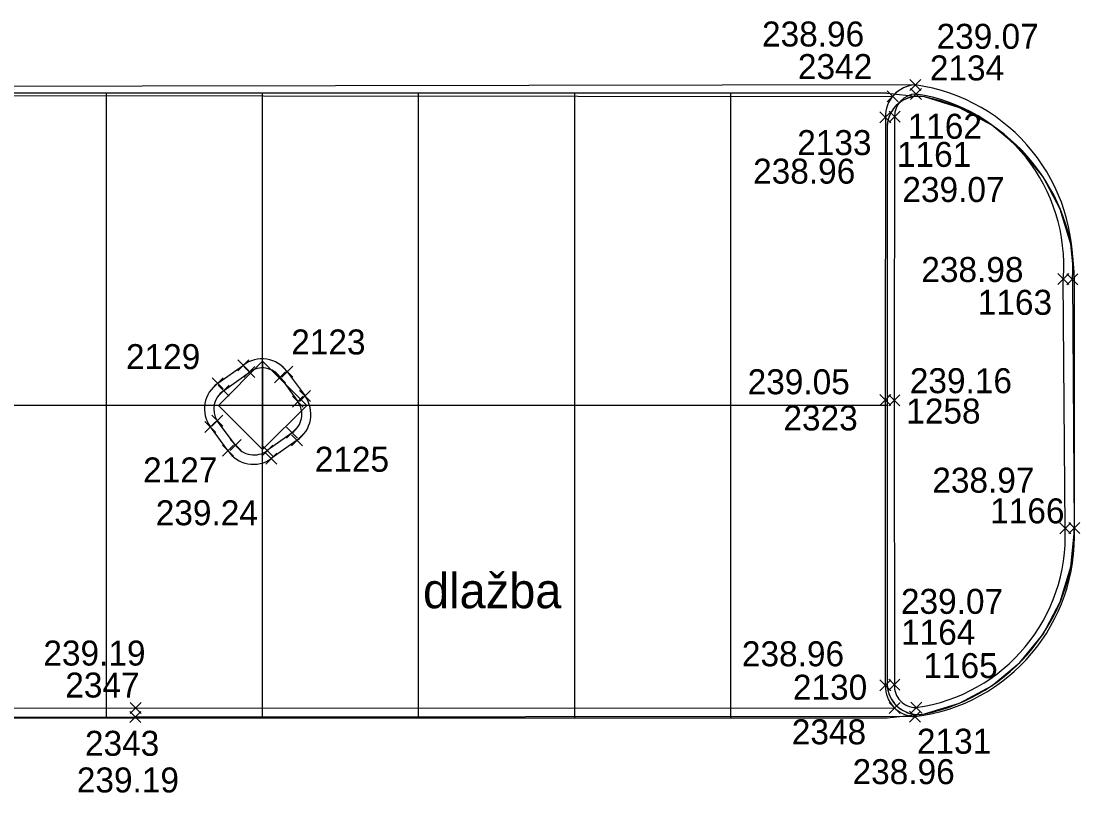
# Model space of a CAD drawing. Extents: x -264222 to -263676, y -1242344 to -1242060.
# Drawn here: x -264148.43 to -264131.48, y -1242229.68 to -1242217.33 of the extents above; entities that cross this region are included whole.
import ezdxf

# ---------------------------------------------------------------- set-up
doc = ezdxf.new("R2010")
doc.units = 0
for name, color, linetype in [('BODY_CISLO', 7, 'Continuous'), ('BODY_SYMBOL', 7, 'Continuous'), ('BODY_VYSKA', 7, 'Continuous'), ('KOORDINACNA_SITUACIA_DSP', 7, 'Continuous'), ('POPIS', 7, 'Continuous'), ('PROJEKT_DRS_OBRUBNIKY_KOMUNIKACIE', 7, 'Continuous'), ('PROJEKT_DRS_TDZ_VODOROVNE', 7, 'Continuous'), ('SO_20-3_OBRUBNIKY_DOLNA_HRANA', 7, 'Continuous'), ('SO_20-3_OBRUBNIKY_HORNA_HRANA', 7, 'Continuous')]:
    doc.layers.add(name, color=color, linetype=linetype)

msp = doc.modelspace()

# ---------------------------------------------------------------- linework, layer by layer
at = {"layer": 'BODY_SYMBOL'}
for p, q in [((-264134.201, -1242218.439), (-264134.025, -1242218.263)), ((-264134.025, -1242218.439), (-264134.201, -1242218.263)), ((-264134.567, -1242218.621), (-264134.391, -1242218.445)), ((-264134.391, -1242218.621), (-264134.567, -1242218.445)), ((-264134.191, -1242218.584), (-264134.015, -1242218.408)), ((-264134.015, -1242218.584), (-264134.191, -1242218.408)), ((-264134.683, -1242218.959), (-264134.507, -1242218.783)), ((-264134.507, -1242218.959), (-264134.683, -1242218.783)), ((-264134.534, -1242218.947), (-264134.358, -1242218.771)), ((-264134.358, -1242218.947), (-264134.534, -1242218.771)), ((-264131.834, -1242221.548), (-264131.658, -1242221.372)), ((-264131.658, -1242221.548), (-264131.834, -1242221.372)), ((-264131.688, -1242221.552), (-264131.512, -1242221.376)), ((-264131.512, -1242221.552), (-264131.688, -1242221.376)), ((-264144.963, -1242222.926), (-264144.787, -1242222.75)), ((-264144.787, -1242222.926), (-264144.963, -1242222.75)), ((-264144.866, -1242223.037), (-264144.69, -1242222.861)), ((-264144.69, -1242223.037), (-264144.866, -1242222.861)), ((-264144.374, -1242223.12), (-264144.198, -1242222.944)), ((-264144.198, -1242223.12), (-264144.374, -1242222.944)), ((-264144.26, -1242223.03), (-264144.084, -1242222.854)), ((-264144.084, -1242223.03), (-264144.26, -1242222.854)), ((-264145.374, -1242223.216), (-264145.198, -1242223.04)), ((-264145.198, -1242223.216), (-264145.374, -1242223.04)), ((-264145.281, -1242223.334), (-264145.105, -1242223.158)), ((-264145.105, -1242223.334), (-264145.281, -1242223.158)), ((-264143.976, -1242223.419), (-264143.8, -1242223.243)), ((-264143.8, -1242223.419), (-264143.976, -1242223.243)), ((-264134.684, -1242223.485), (-264134.508, -1242223.309)), ((-264134.508, -1242223.485), (-264134.684, -1242223.309)), ((-264134.539, -1242223.486), (-264134.363, -1242223.31)), ((-264134.363, -1242223.486), (-264134.539, -1242223.31)), ((-264144.091, -1242223.509), (-264143.915, -1242223.333)), ((-264143.915, -1242223.509), (-264144.091, -1242223.333)), ((-264145.382, -1242223.815), (-264145.206, -1242223.639)), ((-264145.206, -1242223.815), (-264145.382, -1242223.639)), ((-264145.492, -1242223.915), (-264145.316, -1242223.739)), ((-264145.316, -1242223.915), (-264145.492, -1242223.739)), ((-264144.182, -1242224.008), (-264144.006, -1242223.832)), ((-264144.006, -1242224.008), (-264144.182, -1242223.832)), ((-264144.103, -1242224.128), (-264143.927, -1242223.952)), ((-264143.927, -1242224.128), (-264144.103, -1242223.952)), ((-264145.211, -1242224.292), (-264145.035, -1242224.116)), ((-264145.035, -1242224.292), (-264145.211, -1242224.116)), ((-264145.088, -1242224.206), (-264144.912, -1242224.03)), ((-264144.912, -1242224.206), (-264145.088, -1242224.03)), ((-264144.58, -1242224.292), (-264144.404, -1242224.116)), ((-264144.404, -1242224.292), (-264144.58, -1242224.116)), ((-264144.516, -1242224.422), (-264144.34, -1242224.246)), ((-264144.34, -1242224.422), (-264144.516, -1242224.246)), ((-264131.803, -1242225.536), (-264131.627, -1242225.36)), ((-264131.627, -1242225.536), (-264131.803, -1242225.36)), ((-264131.657, -1242225.532), (-264131.481, -1242225.356)), ((-264131.481, -1242225.532), (-264131.657, -1242225.356)), ((-264134.684, -1242228.051), (-264134.508, -1242227.875)), ((-264134.508, -1242228.051), (-264134.684, -1242227.875)), ((-264134.537, -1242228.043), (-264134.361, -1242227.867)), ((-264134.361, -1242228.043), (-264134.537, -1242227.867)), ((-264146.692, -1242228.561), (-264146.516, -1242228.385)), ((-264146.516, -1242228.561), (-264146.692, -1242228.385)), ((-264146.686, -1242228.414), (-264146.51, -1242228.238)), ((-264146.51, -1242228.414), (-264146.686, -1242228.238)), ((-264134.534, -1242228.415), (-264134.358, -1242228.239)), ((-264134.358, -1242228.415), (-264134.534, -1242228.239)), ((-264134.208, -1242228.553), (-264134.032, -1242228.377)), ((-264134.032, -1242228.553), (-264134.208, -1242228.377)), ((-264134.189, -1242228.408), (-264134.013, -1242228.232)), ((-264134.013, -1242228.408), (-264134.189, -1242228.232))]:
    msp.add_line(p, q, dxfattribs=at)
at = {"layer": 'KOORDINACNA_SITUACIA_DSP'}
for p, q in [((-264134.568, -1242219.033), (-264134.568, -1242227.932)), ((-264131.568, -1242225.482), (-264131.568, -1242221.482))]:
    msp.add_line(p, q, dxfattribs=at)
msp.add_lwpolyline([(-264143.861, -1242223.482), (-264144.568, -1242222.775), (-264145.275, -1242223.482), (-264144.568, -1242224.189)], close=True, dxfattribs=at)
for centre, radius, start, end in [((-264134.068, -1242219.033), 0.5, 78.463, 180), ((-264134.568, -1242221.482), 3, 0, 78.463), ((-264134.568, -1242225.482), 3, 281.537, 0), ((-264134.068, -1242227.932), 0.5, 180, 281.537)]:
    msp.add_arc(centre, radius, start, end, dxfattribs=at)
at = {"layer": 'PROJEKT_DRS_OBRUBNIKY_KOMUNIKACIE'}
for p, q in [((-264134.568, -1242218.482), (-264174.568, -1242218.482)), ((-264134.568, -1242218.482), (-264134.068, -1242218.533)), ((-264134.23, -1242218.56), (-264134.311, -1242218.596)), ((-264134.144, -1242218.539), (-264134.23, -1242218.56)), ((-264134.056, -1242218.533), (-264134.144, -1242218.539)), ((-264133.968, -1242218.543), (-264134.056, -1242218.533)), ((-264133.408, -1242218.716), (-264133.968, -1242218.543)), ((-264134.447, -1242218.707), (-264134.499, -1242218.779)), ((-264134.384, -1242218.645), (-264134.447, -1242218.707)), ((-264134.311, -1242218.596), (-264134.384, -1242218.645)), ((-264132.892, -1242218.994), (-264133.408, -1242218.716)), ((-264134.537, -1242218.859), (-264134.56, -1242218.945)), ((-264134.499, -1242218.779), (-264134.537, -1242218.859)), ((-264134.56, -1242218.945), (-264134.568, -1242219.033)), ((-264134.568, -1242219.033), (-264134.568, -1242223.482)), ((-264132.44, -1242219.367), (-264132.892, -1242218.994)), ((-264132.07, -1242219.821), (-264132.44, -1242219.367)), ((-264131.795, -1242220.338), (-264132.07, -1242219.821)), ((-264131.625, -1242220.899), (-264131.795, -1242220.338)), ((-264131.568, -1242221.482), (-264131.625, -1242220.899)), ((-264131.568, -1242225.482), (-264131.568, -1242221.482)), ((-264144.568, -1242222.775), (-264145.275, -1242223.482)), ((-264143.861, -1242223.482), (-264144.568, -1242222.775)), ((-264144.568, -1242222.775), (-264144.568, -1242224.189)), ((-264144.568, -1242224.189), (-264144.568, -1242222.775)), ((-264145.275, -1242223.482), (-264144.568, -1242224.189)), ((-264144.568, -1242224.189), (-264143.861, -1242223.482)), ((-264134.568, -1242223.482), (-264134.568, -1242227.932)), ((-264131.625, -1242226.065), (-264131.568, -1242225.482)), ((-264131.795, -1242226.626), (-264131.625, -1242226.065)), ((-264132.07, -1242227.144), (-264131.795, -1242226.626)), ((-264132.44, -1242227.598), (-264132.07, -1242227.144)), ((-264132.892, -1242227.971), (-264132.44, -1242227.598)), ((-264134.568, -1242227.932), (-264134.56, -1242228.02)), ((-264134.56, -1242228.02), (-264134.537, -1242228.105)), ((-264133.408, -1242228.249), (-264132.892, -1242227.971)), ((-264134.537, -1242228.105), (-264134.499, -1242228.185)), ((-264134.499, -1242228.185), (-264134.447, -1242228.257)), ((-264134.447, -1242228.257), (-264134.384, -1242228.319)), ((-264134.384, -1242228.319), (-264134.311, -1242228.369)), ((-264134.311, -1242228.369), (-264134.23, -1242228.405)), ((-264133.968, -1242228.422), (-264133.408, -1242228.249)), ((-264170.068, -1242228.482), (-264134.568, -1242228.482)), ((-264134.568, -1242228.482), (-264134.068, -1242228.432)), ((-264134.23, -1242228.405), (-264134.144, -1242228.426)), ((-264134.144, -1242228.426), (-264134.056, -1242228.432)), ((-264134.056, -1242228.432), (-264133.968, -1242228.422))]:
    msp.add_line(p, q, dxfattribs=at)
at = {"layer": 'PROJEKT_DRS_TDZ_VODOROVNE'}
for p, q in [((-264147.068, -1242223.482), (-264147.068, -1242218.482)), ((-264144.568, -1242223.482), (-264144.568, -1242218.482)), ((-264142.068, -1242223.482), (-264142.068, -1242218.482)), ((-264139.568, -1242223.482), (-264139.568, -1242218.482)), ((-264137.068, -1242223.482), (-264137.068, -1242218.482)), ((-264134.568, -1242223.482), (-264174.568, -1242223.482)), ((-264147.068, -1242228.482), (-264147.068, -1242223.482)), ((-264144.568, -1242228.482), (-264144.568, -1242223.482)), ((-264142.068, -1242228.482), (-264142.068, -1242223.482)), ((-264139.568, -1242228.482), (-264139.568, -1242223.482)), ((-264137.068, -1242228.482), (-264137.068, -1242223.482))]:
    msp.add_line(p, q, dxfattribs=at)
at = {"layer": 'SO_20-3_OBRUBNIKY_DOLNA_HRANA'}
for p, q in [((-264131.6, -1242221.464), (-264131.569, -1242225.444)), ((-264145.286, -1242223.128), (-264144.875, -1242222.838)), ((-264144.172, -1242222.942), (-264143.888, -1242223.331)), ((-264145.123, -1242224.204), (-264145.404, -1242223.827)), ((-264144.015, -1242224.04), (-264144.428, -1242224.334))]:
    msp.add_line(p, q, dxfattribs=at)
for points in [[(-264134.113, -1242218.351), (-264149.599, -1242218.377), (-264161.594, -1242218.359), (-264175.058, -1242218.33)], [(-264174.683, -1242218.492), (-264161.599, -1242218.503), (-264149.597, -1242218.521), (-264134.479, -1242218.533)], [(-264134.595, -1242218.871), (-264134.596, -1242223.397), (-264134.596, -1242227.963)], [(-264169.7, -1242228.35), (-264157.591, -1242228.333), (-264146.598, -1242228.326), (-264134.446, -1242228.327)], [(-264134.12, -1242228.465), (-264146.604, -1242228.473), (-264157.591, -1242228.481), (-264170.091, -1242228.533)]]:
    msp.add_lwpolyline(points, dxfattribs=at)
for centre, major_axis, ratio, start_param, end_param in [((-264134.09, -1242218.856), (0.02, -0.505), 0.99984, 3.146586, 4.702161), ((-264134.522, -1242221.251), (-2.659, -1.23), 0.999754, 2.635631, 4.139298), ((-264144.574, -1242223.23), (-0.116, -0.48), 0.999745, 2.429115, 4.034199), ((-264144.998, -1242223.536), (0.047, -0.497), 0.999865, 3.662893, 5.240135), ((-264144.297, -1242223.624), (0.169, 0.474), 0.999118, 4.080682, 5.676296), ((-264144.713, -1242223.933), (0.084, -0.485), 0.999589, 5.125377, 6.729557), ((-264134.478, -1242225.574), (1.629, -2.415), 0.999612, 5.812849, 7.305547), ((-264134.104, -1242227.973), (-0.302, -0.388), 0.999983, 5.353406, 6.912327)]:
    msp.add_ellipse(centre, major_axis=major_axis, ratio=ratio, start_param=start_param, end_param=end_param, dxfattribs=at)
at = {"layer": 'SO_20-3_OBRUBNIKY_HORNA_HRANA'}
for p, q in [((-264131.715, -1242225.448), (-264131.746, -1242221.46)), ((-264145.193, -1242223.246), (-264144.778, -1242222.949)), ((-264144.286, -1242223.032), (-264144.003, -1242223.421)), ((-264145, -1242224.118), (-264145.294, -1242223.727)), ((-264144.094, -1242223.92), (-264144.492, -1242224.204))]:
    msp.add_line(p, q, dxfattribs=at)
msp.add_lwpolyline([(-264134.446, -1242218.859), (-264134.451, -1242223.398), (-264134.449, -1242227.955)], dxfattribs=at)
for centre, major_axis, ratio, start_param, end_param in [((-264134.089, -1242218.853), (-0.119, -0.337), 0.99989, 3.520925, 5.068648), ((-264134.518, -1242221.244), (2.733, 0.512), 0.999655, 6.020109, 7.518841), ((-264144.572, -1242223.229), (-0.259, -0.232), 0.998817, 3.011959, 4.615721), ((-264144.997, -1242223.538), (0.052, 0.348), 0.999394, 0.738796, 2.285864), ((-264144.296, -1242223.625), (0.255, 0.25), 0.999854, 4.537797, 6.117226), ((-264144.705, -1242223.917), (0.322, -0.156), 0.998461, 4.191255, 5.801087), ((-264134.491, -1242225.569), (1.77, -2.142), 0.999575, 5.733154, 7.207017), ((-264134.101, -1242227.971), (0.184, -0.297), 0.999814, 4.111444, 5.727218)]:
    msp.add_ellipse(centre, major_axis=major_axis, ratio=ratio, start_param=start_param, end_param=end_param, dxfattribs=at)

# ---------------------------------------------------------------- texts
at = {"layer": 'BODY_CISLO'}
for s, p in [('2342', (-264135.995, -1242218.256)), ('2134', (-264133.882, -1242218.278)), ('1162', (-264134.238, -1242219.212)), ('2133', (-264136.006, -1242219.474)), ('1161', (-264134.409, -1242219.662)), ('1163', (-264133.115, -1242222.031)), ('2123', (-264144.109, -1242222.666)), ('2129', (-264146.755, -1242222.901)), ('2323', (-264136.227, -1242223.882)), ('1258', (-264134.26, -1242223.772)), ('2125', (-264143.732, -1242224.544)), ('2127', (-264146.481, -1242224.715)), ('1166', (-264132.916, -1242225.37)), ('1164', (-264134.344, -1242227.314)), ('1165', (-264133.986, -1242227.848)), ('2347', (-264147.727, -1242228.159)), ('2130', (-264136.075, -1242228.194)), ('2348', (-264136.093, -1242228.908)), ('2343', (-264147.412, -1242229.092)), ('2131', (-264134.089, -1242229.059))]:
    msp.add_text(s, height=0.4, dxfattribs=at).set_placement(p)
at = {"layer": 'BODY_VYSKA'}
for s, p in [('238.96', (-264136.57, -1242217.735)), ('239.07', (-264133.775, -1242217.772)), ('238.96', (-264136.712, -1242219.931)), ('239.07', (-264134.322, -1242220.225)), ('238.98', (-264134.019, -1242221.506)), ('239.05', (-264136.8, -1242223.303)), ('239.16', (-264134.203, -1242223.286)), ('238.97', (-264133.843, -1242224.879)), ('239.24', (-264146.278, -1242225.401)), ('239.07', (-264134.345, -1242226.819)), ('239.19', (-264148.078, -1242227.647)), ('238.96', (-264136.892, -1242227.659)), ('238.96', (-264135.12, -1242229.546)), ('239.19', (-264147.542, -1242229.679))]:
    msp.add_text(s, height=0.4, dxfattribs=at).set_placement(p)
at = {"layer": 'POPIS'}
msp.add_text('dlažba', height=0.5625, rotation=360, dxfattribs=at).set_placement((-264141.998, -1242226.729))

doc.saveas('drawing.dxf')
